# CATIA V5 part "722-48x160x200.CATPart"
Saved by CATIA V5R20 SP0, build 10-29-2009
Part number: 722-48x160x200
Definition: NONE
Nomenclature: 722-48x160x200
Source: Unknown
Description: 722-48x160x200
Bounding box of the stored display mesh (mm): x -24 to 24, y -23.825 to 23.825, z -142 to 58
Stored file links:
  C:\Users\Utente\Desktop\IO LAVORO\3D X SITO CF\X SITO\722\722-48x160x200.CATPart
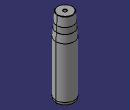
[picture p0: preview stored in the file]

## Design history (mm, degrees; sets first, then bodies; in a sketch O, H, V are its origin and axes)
Body1 "722-48x160x200" (main body)
  Solid1: solid without history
